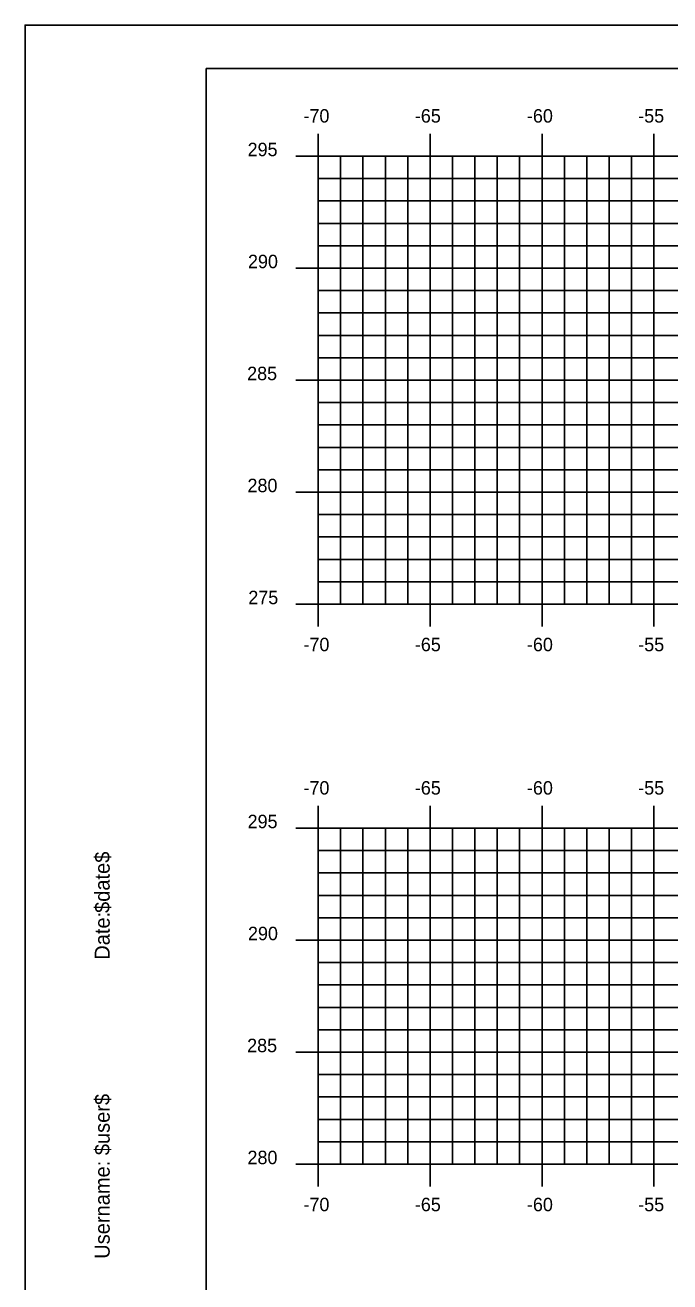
# Model space of a CAD drawing. Extents: x 852672 to 852842, y 366268 to 366378.
# Drawn here: x 852672 to 852700.8, y 366322.1 to 366378.2 of the extents above; entities that cross this region are included whole.
import ezdxf

# ---------------------------------------------------------------- set-up
doc = ezdxf.new("R2010")
doc.units = 0
for name, color, linetype in [('BORDER', 7, 'Continuous'), ('H_V ANNOTATION', 7, 'Continuous'), ('MAJOR', 7, 'Continuous'), ('MINOR', 7, 'Continuous'), ('PLOT BOUNDARY', 7, 'Continuous')]:
    doc.layers.add(name, color=color, linetype=linetype)

msp = doc.modelspace()

# ---------------------------------------------------------------- linework, layer by layer
at = {"layer": 'BORDER'}
for p, q in [((852840.097, 366376.236), (852680.097, 366376.236)), ((852680.097, 366376.236), (852680.097, 366271.236))]:
    msp.add_line(p, q, dxfattribs=at)
at = {"layer": 'MAJOR'}
for p, q in [((852685.096, 366373.329), (852685.096, 366372.327)), ((852690.096, 366373.329), (852690.096, 366372.327)), ((852695.096, 366373.329), (852695.096, 366372.327)), ((852700.096, 366373.329), (852700.096, 366372.327)), ((852684.094, 366372.327), (852685.096, 366372.327)), ((852685.096, 366372.327), (852825.096, 366372.327)), ((852685.096, 366352.327), (852685.096, 366372.327)), ((852685.096, 366352.327), (852685.096, 366372.327)), ((852685.096, 366372.327), (852825.096, 366372.327)), ((852690.096, 366352.327), (852690.096, 366372.327)), ((852695.096, 366352.327), (852695.096, 366372.327)), ((852700.096, 366352.327), (852700.096, 366372.327)), ((852684.094, 366367.327), (852685.096, 366367.327)), ((852685.096, 366367.327), (852825.096, 366367.327)), ((852684.094, 366362.327), (852685.096, 366362.327)), ((852685.096, 366362.327), (852825.096, 366362.327)), ((852684.094, 366357.327), (852685.096, 366357.327)), ((852685.096, 366357.327), (852825.096, 366357.327)), ((852684.094, 366352.327), (852685.096, 366352.327)), ((852685.096, 366352.327), (852825.096, 366352.327)), ((852685.096, 366352.327), (852825.096, 366352.327)), ((852685.096, 366351.325), (852685.096, 366352.327)), ((852690.096, 366351.325), (852690.096, 366352.327)), ((852695.096, 366351.325), (852695.096, 366352.327)), ((852700.096, 366351.325), (852700.096, 366352.327)), ((852685.096, 366343.329), (852685.096, 366342.327)), ((852690.096, 366343.329), (852690.096, 366342.327)), ((852695.096, 366343.329), (852695.096, 366342.327)), ((852700.096, 366343.329), (852700.096, 366342.327)), ((852684.094, 366342.327), (852685.096, 366342.327)), ((852685.096, 366342.327), (852825.096, 366342.327)), ((852685.096, 366327.327), (852685.096, 366342.327)), ((852685.096, 366327.327), (852685.096, 366342.327)), ((852685.096, 366342.327), (852825.096, 366342.327)), ((852690.096, 366327.327), (852690.096, 366342.327)), ((852695.096, 366327.327), (852695.096, 366342.327)), ((852700.096, 366327.327), (852700.096, 366342.327)), ((852684.094, 366337.327), (852685.096, 366337.327)), ((852685.096, 366337.327), (852825.096, 366337.327)), ((852684.094, 366332.327), (852685.096, 366332.327)), ((852685.096, 366332.327), (852825.096, 366332.327)), ((852684.094, 366327.327), (852685.096, 366327.327)), ((852685.096, 366327.327), (852825.096, 366327.327)), ((852685.096, 366327.327), (852825.096, 366327.327)), ((852685.096, 366326.325), (852685.096, 366327.327)), ((852690.096, 366326.325), (852690.096, 366327.327)), ((852695.096, 366326.325), (852695.096, 366327.327)), ((852700.096, 366326.325), (852700.096, 366327.327))]:
    msp.add_line(p, q, dxfattribs=at)
at = {"layer": 'MINOR'}
for p, q in [((852686.096, 366352.327), (852686.096, 366372.327)), ((852687.096, 366352.327), (852687.096, 366372.327)), ((852688.096, 366352.327), (852688.096, 366372.327)), ((852689.096, 366352.327), (852689.096, 366372.327)), ((852691.096, 366352.327), (852691.096, 366372.327)), ((852692.096, 366352.327), (852692.096, 366372.327)), ((852693.096, 366352.327), (852693.096, 366372.327)), ((852694.096, 366352.327), (852694.096, 366372.327)), ((852696.096, 366352.327), (852696.096, 366372.327)), ((852697.096, 366352.327), (852697.096, 366372.327)), ((852698.096, 366352.327), (852698.096, 366372.327)), ((852699.096, 366352.327), (852699.096, 366372.327)), ((852685.096, 366371.327), (852825.096, 366371.327)), ((852685.096, 366371.327), (852686.098, 366371.327)), ((852685.096, 366370.327), (852825.096, 366370.327)), ((852685.096, 366370.327), (852686.098, 366370.327)), ((852685.096, 366369.327), (852825.096, 366369.327)), ((852685.096, 366369.327), (852686.098, 366369.327)), ((852685.096, 366368.327), (852825.096, 366368.327)), ((852685.096, 366368.327), (852686.098, 366368.327)), ((852685.096, 366366.327), (852825.096, 366366.327)), ((852685.096, 366366.327), (852686.098, 366366.327)), ((852685.096, 366365.327), (852825.096, 366365.327)), ((852685.096, 366365.327), (852686.098, 366365.327)), ((852685.096, 366364.327), (852825.096, 366364.327)), ((852685.096, 366364.327), (852686.098, 366364.327)), ((852685.096, 366363.327), (852825.096, 366363.327)), ((852685.096, 366363.327), (852686.098, 366363.327)), ((852685.096, 366361.327), (852825.096, 366361.327)), ((852685.096, 366361.327), (852686.098, 366361.327)), ((852685.096, 366360.327), (852825.096, 366360.327)), ((852685.096, 366360.327), (852686.098, 366360.327)), ((852685.096, 366359.327), (852825.096, 366359.327)), ((852685.096, 366359.327), (852686.098, 366359.327)), ((852685.096, 366358.327), (852825.096, 366358.327)), ((852685.096, 366358.327), (852686.098, 366358.327)), ((852685.096, 366356.327), (852825.096, 366356.327)), ((852685.096, 366356.327), (852686.098, 366356.327)), ((852685.096, 366355.327), (852825.096, 366355.327)), ((852685.096, 366355.327), (852686.098, 366355.327)), ((852685.096, 366354.327), (852825.096, 366354.327)), ((852685.096, 366354.327), (852686.098, 366354.327)), ((852685.096, 366353.327), (852825.096, 366353.327)), ((852685.096, 366353.327), (852686.098, 366353.327)), ((852686.096, 366327.327), (852686.096, 366342.327)), ((852687.096, 366327.327), (852687.096, 366342.327)), ((852688.096, 366327.327), (852688.096, 366342.327)), ((852689.096, 366327.327), (852689.096, 366342.327)), ((852691.096, 366327.327), (852691.096, 366342.327)), ((852692.096, 366327.327), (852692.096, 366342.327)), ((852693.096, 366327.327), (852693.096, 366342.327)), ((852694.096, 366327.327), (852694.096, 366342.327)), ((852696.096, 366327.327), (852696.096, 366342.327)), ((852697.096, 366327.327), (852697.096, 366342.327)), ((852698.096, 366327.327), (852698.096, 366342.327)), ((852699.096, 366327.327), (852699.096, 366342.327)), ((852685.096, 366341.327), (852825.096, 366341.327)), ((852685.096, 366341.327), (852686.098, 366341.327)), ((852685.096, 366340.327), (852825.096, 366340.327)), ((852685.096, 366340.327), (852686.098, 366340.327)), ((852685.096, 366339.327), (852825.096, 366339.327)), ((852685.096, 366339.327), (852686.098, 366339.327)), ((852685.096, 366338.327), (852825.096, 366338.327)), ((852685.096, 366338.327), (852686.098, 366338.327)), ((852685.096, 366336.327), (852825.096, 366336.327)), ((852685.096, 366336.327), (852686.098, 366336.327)), ((852685.096, 366335.327), (852825.096, 366335.327)), ((852685.096, 366335.327), (852686.098, 366335.327)), ((852685.096, 366334.327), (852825.096, 366334.327)), ((852685.096, 366334.327), (852686.098, 366334.327)), ((852685.096, 366333.327), (852825.096, 366333.327)), ((852685.096, 366333.327), (852686.098, 366333.327)), ((852685.096, 366331.327), (852825.096, 366331.327)), ((852685.096, 366331.327), (852686.098, 366331.327)), ((852685.096, 366330.327), (852825.096, 366330.327)), ((852685.096, 366330.327), (852686.098, 366330.327)), ((852685.096, 366329.327), (852825.096, 366329.327)), ((852685.096, 366329.327), (852686.098, 366329.327)), ((852685.096, 366328.327), (852825.096, 366328.327)), ((852685.096, 366328.327), (852686.098, 366328.327))]:
    msp.add_line(p, q, dxfattribs=at)
at = {"layer": 'PLOT BOUNDARY'}
msp.add_lwpolyline([(852672.003, 366268.177), (852842.003, 366268.177), (852842.003, 366378.177), (852672.003, 366378.177)], close=True, dxfattribs=at)

# ---------------------------------------------------------------- texts
at = {"layer": 'BORDER'}
for s, p in [('$date$', (852675.782, 366338.542)), ('Date:', (852675.782, 366336.453)), ('$user$', (852675.782, 366327.728)), ('Username:', (852675.782, 366323.104))]:
    msp.add_text(s, height=0.6696, rotation=90, dxfattribs=at).set_placement(p)
at = {"layer": 'H_V ANNOTATION'}
for s, p in [('-70', (852684.438, 366373.827)), ('-65', (852689.414, 366373.827)), ('-60', (852694.422, 366373.827)), ('-55', (852699.393, 366373.827)), ('295', (852681.943, 366372.327)), ('290', (852681.959, 366367.327)), ('285', (852681.921, 366362.327)), ('280', (852681.937, 366357.327)), ('275', (852681.974, 366352.327)), ('-70', (852684.438, 366350.227)), ('-65', (852689.414, 366350.227)), ('-60', (852694.422, 366350.227)), ('-55', (852699.393, 366350.227)), ('-70', (852684.438, 366343.827)), ('-65', (852689.414, 366343.827)), ('-60', (852694.422, 366343.827)), ('-55', (852699.393, 366343.827)), ('295', (852681.943, 366342.327)), ('290', (852681.959, 366337.327)), ('285', (852681.921, 366332.327)), ('280', (852681.937, 366327.327)), ('-70', (852684.438, 366325.227)), ('-65', (852689.414, 366325.227)), ('-60', (852694.422, 366325.227)), ('-55', (852699.393, 366325.227))]:
    msp.add_text(s, height=0.6, dxfattribs=at).set_placement(p)

doc.saveas('drawing.dxf')
